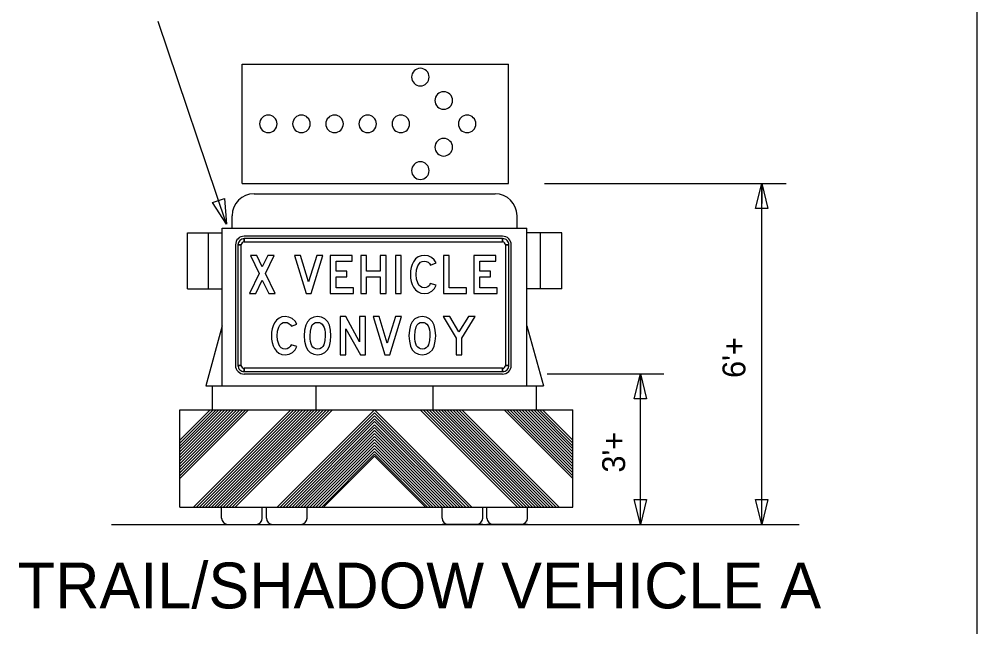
# Model space of a CAD drawing. Extents: x -747 to 834, y -5485 to -3577.
# Drawn here: x 65.7 to 316.6, y -4697.2 to -4538 of the extents above; entities that cross this region are included whole.
import ezdxf

# ---------------------------------------------------------------- set-up
doc = ezdxf.new("R2010")
doc.units = 0
doc.layers.add('Working Level 1', color=7, linetype='Continuous')

msp = doc.modelspace()

# ---------------------------------------------------------------- linework, layer by layer
at = {"layer": 'Working Level 1'}
for p, q in [((316.57, -4442.19), (316.57, -5484.51)), ((120, -4591.66), (102.14, -4538.59)), ((124.09, -4549.76), (193.86, -4549.76)), ((124.09, -4581.05), (124.09, -4549.76)), ((193.86, -4581.05), (193.86, -4549.76)), ((124.09, -4581.05), (193.86, -4581.05)), ((203.33, -4581.05), (266.6, -4581.05)), ((260.24, -4670.36), (260.24, -4581.05)), ((260.24, -4581.05), (260.24, -4586.29)), ((127.24, -4583.73), (190.38, -4583.73)), ((121.49, -4592.76), (121.49, -4589.46)), ((196.12, -4592.76), (196.12, -4589.46)), ((118.89, -4634.02), (118.89, -4592.76)), ((118.89, -4592.76), (198.72, -4592.76)), ((198.72, -4634.02), (198.72, -4592.76)), ((109.78, -4608.59), (109.78, -4593.92)), ((109.78, -4593.92), (118.89, -4593.92)), ((115.3, -4608.59), (115.3, -4593.92)), ((192.35, -4594.83), (124.64, -4594.83)), ((124.64, -4596.33), (124.64, -4595.46)), ((192.35, -4595.46), (192.35, -4596.33)), ((207.83, -4593.92), (198.72, -4593.92)), ((202.31, -4608.59), (202.31, -4593.92)), ((207.83, -4608.59), (207.83, -4593.92)), ((122.38, -4597.09), (122.38, -4628.69)), ((123.01, -4597.09), (123.88, -4597.09)), ((193.1, -4597.09), (193.98, -4597.09)), ((194.61, -4628.69), (194.61, -4597.09)), ((109.78, -4608.59), (118.89, -4608.59)), ((207.83, -4608.59), (198.72, -4608.59)), ((118.89, -4618.31), (114.58, -4634.02)), ((198.72, -4618.31), (203.04, -4634.02)), ((123.88, -4628.69), (123.01, -4628.69)), ((124.64, -4630.32), (124.64, -4629.44)), ((192.35, -4629.44), (192.35, -4630.32)), ((193.98, -4628.69), (193.1, -4628.69)), ((124.64, -4630.94), (192.35, -4630.94)), ((203.98, -4630.94), (234.6, -4630.94)), ((228.43, -4670.36), (228.43, -4630.94)), ((228.43, -4630.94), (228.43, -4636.27)), ((114.58, -4634.02), (203.04, -4634.02)), ((116.37, -4640.33), (116.37, -4634.02)), ((143.49, -4640.33), (143.49, -4634.14)), ((174.12, -4640.33), (174.12, -4634.14)), ((201.24, -4640.33), (201.24, -4634.02)), ((107.8, -4640.33), (210.75, -4640.33)), ((107.8, -4640.33), (210.75, -4640.33)), ((107.8, -4640.33), (210.75, -4640.33)), ((107.8, -4640.33), (210.75, -4640.33)), ((107.8, -4665.83), (107.8, -4640.33)), ((107.8, -4648.31), (115.78, -4640.33)), ((107.8, -4657.59), (125.06, -4640.33)), ((107.8, -4656.81), (124.28, -4640.33)), ((107.8, -4656.02), (123.5, -4640.33)), ((107.8, -4655.25), (122.73, -4640.33)), ((107.8, -4654.47), (121.95, -4640.33)), ((107.8, -4653.69), (121.16, -4640.33)), ((107.8, -4652.92), (120.39, -4640.33)), ((107.8, -4652.14), (119.61, -4640.33)), ((107.8, -4651.36), (118.83, -4640.33)), ((107.8, -4650.58), (118.05, -4640.33)), ((107.8, -4649.81), (117.28, -4640.33)), ((107.8, -4649.03), (116.5, -4640.33)), ((107.8, -4658.36), (125.81, -4640.35)), ((111.39, -4665.83), (136.89, -4640.33)), ((112.17, -4665.83), (137.66, -4640.33)), ((112.95, -4665.83), (138.45, -4640.33)), ((113.73, -4665.83), (139.23, -4640.33)), ((114.5, -4665.83), (140, -4640.33)), ((115.28, -4665.83), (140.78, -4640.33)), ((116.06, -4665.83), (141.56, -4640.33)), ((116.84, -4665.83), (142.34, -4640.33)), ((117.61, -4665.83), (143.11, -4640.33)), ((118.39, -4665.83), (143.89, -4640.33)), ((119.17, -4665.83), (144.67, -4640.33)), ((119.94, -4665.83), (145.44, -4640.33)), ((120.72, -4665.83), (146.22, -4640.33)), ((121.51, -4665.83), (146.99, -4640.34)), ((122.28, -4665.83), (147.78, -4640.33)), ((133.31, -4665.83), (158.81, -4640.33)), ((184.3, -4665.83), (158.81, -4640.33)), ((196.27, -4665.83), (170.77, -4640.33)), ((197.04, -4665.83), (171.56, -4640.34)), ((197.82, -4665.83), (172.33, -4640.33)), ((198.6, -4665.83), (173.11, -4640.33)), ((199.37, -4665.83), (173.88, -4640.33)), ((200.16, -4665.83), (174.66, -4640.33)), ((200.94, -4665.83), (175.44, -4640.33)), ((201.71, -4665.83), (176.21, -4640.33)), ((202.49, -4665.83), (176.99, -4640.33)), ((203.27, -4665.83), (177.77, -4640.33)), ((204.05, -4665.83), (178.55, -4640.33)), ((204.82, -4665.83), (179.32, -4640.33)), ((205.6, -4665.83), (180.1, -4640.33)), ((206.38, -4665.83), (180.88, -4640.33)), ((207.16, -4665.83), (181.66, -4640.33)), ((210.75, -4658.36), (192.74, -4640.35)), ((210.75, -4657.59), (193.49, -4640.33)), ((210.75, -4656.81), (194.27, -4640.33)), ((210.75, -4656.02), (195.05, -4640.33)), ((210.75, -4655.25), (195.82, -4640.33)), ((210.75, -4654.47), (196.6, -4640.33)), ((210.75, -4653.69), (197.38, -4640.33)), ((210.75, -4652.92), (198.15, -4640.33)), ((210.75, -4652.14), (198.93, -4640.33)), ((210.75, -4651.36), (199.72, -4640.33)), ((210.75, -4650.58), (200.5, -4640.33)), ((210.75, -4649.81), (201.27, -4640.33)), ((210.75, -4649.03), (202.05, -4640.33)), ((210.75, -4648.31), (202.77, -4640.33)), ((210.75, -4665.83), (210.75, -4640.33)), ((134.08, -4665.83), (158.81, -4641.1)), ((134.86, -4665.83), (158.81, -4641.88)), ((135.65, -4665.83), (158.81, -4642.66)), ((183.49, -4665.78), (158.81, -4641.1)), ((182.75, -4665.83), (158.81, -4641.88)), ((181.97, -4665.83), (158.81, -4642.66)), ((136.42, -4665.83), (158.81, -4643.43)), ((137.2, -4665.83), (158.81, -4644.22)), ((137.98, -4665.83), (158.81, -4645)), ((138.75, -4665.83), (158.81, -4645.77)), ((181.2, -4665.83), (158.81, -4643.43)), ((180.42, -4665.83), (158.81, -4644.22)), ((179.64, -4665.83), (158.81, -4645)), ((178.87, -4665.83), (158.81, -4645.77)), ((139.53, -4665.83), (158.81, -4646.55)), ((140.31, -4665.83), (158.81, -4647.33)), ((141.09, -4665.83), (158.81, -4648.11)), ((178.09, -4665.83), (158.81, -4646.55)), ((177.31, -4665.83), (158.81, -4647.33)), ((176.53, -4665.83), (158.81, -4648.11)), ((141.86, -4665.83), (158.81, -4648.88)), ((142.64, -4665.83), (158.81, -4649.66)), ((143.42, -4665.83), (158.81, -4650.44)), ((175.76, -4665.83), (158.81, -4648.88)), ((174.98, -4665.83), (158.81, -4649.66)), ((174.2, -4665.83), (158.81, -4650.44)), ((144.19, -4665.83), (158.81, -4651.21)), ((144.97, -4665.83), (158.81, -4651.99)), ((145.62, -4665.68), (158.81, -4652.49)), ((173.43, -4665.83), (158.81, -4651.21)), ((172.64, -4665.83), (158.81, -4651.99)), ((172.14, -4665.83), (158.81, -4652.49)), ((107.8, -4665.83), (210.75, -4665.83)), ((107.8, -4665.83), (210.75, -4665.83)), ((107.8, -4665.83), (210.75, -4665.83)), ((107.8, -4665.83), (210.75, -4665.83)), ((118.74, -4668.71), (118.74, -4665.83)), ((129.38, -4668.71), (129.38, -4665.83)), ((130.48, -4668.71), (130.48, -4665.83)), ((141.11, -4668.71), (141.11, -4665.83)), ((176.5, -4668.71), (176.5, -4665.83)), ((187.14, -4668.71), (187.14, -4665.83)), ((188.24, -4668.71), (188.24, -4665.83)), ((198.87, -4668.71), (198.87, -4665.83)), ((89.92, -4670.36), (270.03, -4670.36)), ((118.74, -4670.36), (129.38, -4670.36)), ((118.74, -4670.36), (129.38, -4670.36)), ((118.74, -4670.36), (129.38, -4670.36)), ((118.74, -4670.36), (129.38, -4670.36)), ((130.48, -4670.36), (141.11, -4670.36)), ((130.48, -4670.36), (141.11, -4670.36)), ((130.48, -4670.36), (141.11, -4670.36)), ((130.48, -4670.36), (141.11, -4670.36)), ((187.14, -4670.36), (176.5, -4670.36)), ((187.14, -4670.36), (176.5, -4670.36)), ((187.14, -4670.36), (176.5, -4670.36)), ((187.14, -4670.36), (176.5, -4670.36)), ((198.87, -4670.36), (188.24, -4670.36)), ((198.87, -4670.36), (188.24, -4670.36)), ((198.87, -4670.36), (188.24, -4670.36)), ((198.87, -4670.36), (188.24, -4670.36))]:
    msp.add_line(p, q, dxfattribs=at)
for points in [[(258.61, -4587.55), (260.24, -4581.05), (261.86, -4587.55)], [(119.46, -4584.98), (120, -4591.66), (116.38, -4586.02)], [(192.35, -4595.46), (124.64, -4595.46), (124.64, -4596.33), (192.35, -4596.33), (192.35, -4595.46)], [(123.01, -4597.09), (123.01, -4628.69), (123.88, -4628.69), (123.88, -4597.09), (123.01, -4597.09)], [(193.98, -4628.69), (193.98, -4597.09), (193.1, -4597.09), (193.1, -4628.69), (193.98, -4628.69)], [(132.74, -4609.88), (130.24, -4604.62), (132.53, -4599.85), (130.86, -4599.85), (129.4, -4602.87), (127.96, -4599.85), (126.28, -4599.85), (128.56, -4604.63), (126.05, -4609.88), (127.72, -4609.88), (129.4, -4606.39), (131.07, -4609.88)], [(145.27, -4599.85), (143.69, -4599.85), (141.53, -4606.78), (139.38, -4599.85), (137.8, -4599.85), (140.91, -4609.88), (142.16, -4609.88)], [(153.27, -4608.36), (148.72, -4608.36), (148.72, -4605.52), (151.56, -4605.52), (151.56, -4604.01), (148.72, -4604.01), (148.72, -4601.36), (152.97, -4601.36), (152.97, -4599.85), (147.21, -4599.85), (147.21, -4609.88), (153.27, -4609.88)], [(161.83, -4609.88), (161.83, -4599.85), (160.31, -4599.85), (160.31, -4604.01), (156.71, -4604.01), (156.71, -4599.85), (155.2, -4599.85), (155.2, -4609.88), (156.71, -4609.88), (156.71, -4605.52), (160.31, -4605.52), (160.31, -4609.88)], [(165.81, -4609.88), (165.81, -4599.85), (164.29, -4599.85), (164.29, -4609.88)], [(174.91, -4607.65), (173.39, -4607.27), (173.17, -4607.71), (172.8, -4608.06), (172.33, -4608.29), (171.81, -4608.36), (171.28, -4608.28), (170.83, -4608.04), (170.44, -4607.64), (170.14, -4607.09), (169.83, -4606.06), (169.73, -4604.86), (169.83, -4603.66), (170.15, -4602.63), (170.47, -4602.07), (170.86, -4601.68), (171.32, -4601.44), (171.86, -4601.36), (172.36, -4601.43), (172.81, -4601.64), (173.19, -4601.97), (173.45, -4602.39), (174.91, -4601.82), (174.42, -4601.01), (173.7, -4600.38), (172.83, -4599.98), (171.88, -4599.85), (170.99, -4599.95), (170.23, -4600.27), (169.57, -4600.79), (169.02, -4601.52), (168.66, -4602.24), (168.41, -4603.04), (168.26, -4603.91), (168.21, -4604.86), (168.26, -4605.8), (168.41, -4606.67), (168.66, -4607.46), (169.01, -4608.19), (169.55, -4608.93), (170.2, -4609.45), (170.96, -4609.77), (171.83, -4609.88), (172.85, -4609.72), (173.77, -4609.26), (174.48, -4608.55)], [(182.9, -4609.88), (182.9, -4608.36), (178.35, -4608.36), (178.35, -4599.85), (176.83, -4599.85), (176.83, -4609.88)], [(190.89, -4608.36), (186.34, -4608.36), (186.34, -4605.52), (189.18, -4605.52), (189.18, -4604.01), (186.34, -4604.01), (186.34, -4601.36), (190.59, -4601.36), (190.59, -4599.85), (184.83, -4599.85), (184.83, -4609.88), (190.89, -4609.88)], [(138.46, -4623.7), (136.95, -4623.32), (136.72, -4623.76), (136.35, -4624.11), (135.88, -4624.34), (135.36, -4624.41), (134.83, -4624.33), (134.38, -4624.09), (134, -4623.7), (133.69, -4623.14), (133.38, -4622.11), (133.28, -4620.91), (133.39, -4619.71), (133.7, -4618.68), (134.02, -4618.13), (134.41, -4617.73), (134.87, -4617.49), (135.41, -4617.41), (135.91, -4617.48), (136.37, -4617.69), (136.75, -4618.02), (137.01, -4618.44), (138.46, -4617.87), (137.97, -4617.06), (137.26, -4616.43), (136.39, -4616.03), (135.43, -4615.9), (134.55, -4616), (133.78, -4616.32), (133.12, -4616.84), (132.58, -4617.57), (132.22, -4618.29), (131.97, -4619.09), (131.82, -4619.96), (131.77, -4620.91), (131.81, -4621.85), (131.97, -4622.72), (132.21, -4623.52), (132.57, -4624.24), (133.1, -4624.98), (133.75, -4625.5), (134.51, -4625.82), (135.38, -4625.93), (136.4, -4625.77), (137.32, -4625.31), (138.04, -4624.6)], [(147.39, -4620.91), (147.29, -4619.48), (146.98, -4618.14), (146.53, -4617.23), (145.81, -4616.51), (144.9, -4616.05), (143.88, -4615.9), (142.86, -4616.05), (141.96, -4616.51), (141.25, -4617.23), (140.8, -4618.14), (140.49, -4619.48), (140.39, -4620.91), (140.49, -4622.33), (140.8, -4623.67), (141.25, -4624.58), (141.96, -4625.3), (142.86, -4625.77), (143.88, -4625.93), (144.9, -4625.77), (145.81, -4625.31), (146.52, -4624.6), (146.98, -4623.69), (147.28, -4622.34)], [(145.88, -4620.91), (145.79, -4622.13), (145.52, -4623.26), (145.28, -4623.74), (144.9, -4624.1), (144.43, -4624.34), (143.9, -4624.41), (143.43, -4624.36), (143.02, -4624.19), (142.68, -4623.92), (142.4, -4623.54), (142.18, -4623.05), (142.03, -4622.44), (141.93, -4621.73), (141.9, -4620.91), (141.99, -4619.7), (142.26, -4618.57), (142.5, -4618.1), (142.87, -4617.73), (143.35, -4617.49), (143.9, -4617.41), (144.36, -4617.47), (144.76, -4617.63), (145.1, -4617.9), (145.38, -4618.29), (145.6, -4618.78), (145.75, -4619.38), (145.84, -4620.09)], [(156.42, -4625.93), (156.42, -4615.9), (154.9, -4615.9), (154.9, -4622.49), (151.25, -4615.9), (149.79, -4615.9), (149.79, -4625.93), (151.31, -4625.93), (151.31, -4619.12), (155.08, -4625.93)], [(165.89, -4615.9), (164.3, -4615.9), (162.15, -4622.83), (160, -4615.9), (158.42, -4615.9), (161.52, -4625.93), (162.77, -4625.93)], [(174.82, -4620.91), (174.72, -4619.48), (174.41, -4618.14), (173.96, -4617.23), (173.24, -4616.51), (172.34, -4616.05), (171.32, -4615.9), (170.3, -4616.05), (169.39, -4616.51), (168.68, -4617.23), (168.23, -4618.14), (167.92, -4619.48), (167.82, -4620.91), (167.92, -4622.33), (168.23, -4623.67), (168.68, -4624.58), (169.39, -4625.3), (170.3, -4625.77), (171.32, -4625.93), (172.33, -4625.77), (173.24, -4625.31), (173.95, -4624.6), (174.41, -4623.69), (174.72, -4622.34)], [(173.31, -4620.91), (173.22, -4622.13), (172.95, -4623.26), (172.71, -4623.74), (172.34, -4624.1), (171.86, -4624.34), (171.33, -4624.41), (170.86, -4624.36), (170.45, -4624.19), (170.11, -4623.92), (169.83, -4623.54), (169.61, -4623.05), (169.46, -4622.44), (169.36, -4621.73), (169.33, -4620.91), (169.42, -4619.7), (169.69, -4618.57), (169.93, -4618.1), (170.3, -4617.73), (170.78, -4617.49), (171.33, -4617.41), (171.79, -4617.47), (172.19, -4617.63), (172.53, -4617.9), (172.81, -4618.29), (173.03, -4618.78), (173.18, -4619.38), (173.28, -4620.09)], [(185.16, -4615.9), (183.38, -4615.9), (180.92, -4619.9), (178.52, -4615.9), (176.75, -4615.9), (180.16, -4621.53), (180.16, -4625.93), (181.68, -4625.93), (181.68, -4621.57)], [(124.64, -4630.32), (192.35, -4630.32), (192.35, -4629.44), (124.64, -4629.44), (124.64, -4630.32)], [(226.8, -4637.44), (228.43, -4630.94), (230.05, -4637.44)], [(230.05, -4663.86), (228.43, -4670.36), (226.8, -4663.86)], [(261.86, -4663.86), (260.24, -4670.36), (258.61, -4663.86)]]:
    msp.add_lwpolyline(points, close=True, dxfattribs=at)
for centre, radius, start, end in [((170.81, -4553.14), 2.3, 0, 180), ((170.81, -4553.14), 2.3, 180, 0), ((176.93, -4559.27), 2.3, 0, 180), ((176.93, -4559.27), 2.3, 180, 0), ((130.97, -4565.4), 2.3, 0, 180), ((130.97, -4565.4), 2.3, 180, 0), ((139.65, -4565.4), 2.3, 0, 180), ((139.65, -4565.4), 2.3, 180, 0), ((148.33, -4565.4), 2.3, 0, 180), ((148.33, -4565.4), 2.3, 180, 0), ((157.01, -4565.4), 2.3, 0, 180), ((157.01, -4565.4), 2.3, 180, 0), ((165.69, -4565.4), 2.3, 0, 180), ((165.69, -4565.4), 2.3, 180, 0), ((183.05, -4565.4), 2.3, 0, 180), ((183.05, -4565.4), 2.3, 180, 0), ((176.93, -4571.52), 2.3, 0, 180), ((176.93, -4571.52), 2.3, 180, 0), ((170.81, -4577.64), 2.3, 0, 180), ((170.81, -4577.64), 2.3, 180, 0), ((127.23, -4589.46), 5.74, 90, 180), ((190.38, -4589.46), 5.74, 0, 90), ((124.64, -4597.09), 2.26, 90.0002, 179.9998), ((124.64, -4597.09), 1.63, 90.0002, 179.9998), ((192.35, -4597.09), 2.26, 0, 90.0002), ((192.35, -4597.09), 1.63, 0, 90.0002), ((124.64, -4597.09), 0.752, 90.0002, 179.9998), ((192.35, -4597.09), 0.752, 0, 90.0002), ((124.64, -4628.69), 2.26, 179.9998, 270.0001), ((124.64, -4628.69), 1.63, 179.9998, 270.0001), ((124.64, -4628.69), 0.752, 179.9998, 270.0001), ((192.35, -4628.69), 2.26, 270.0001, 0.0003), ((192.35, -4628.69), 1.63, 270.0001, 0.0003), ((192.35, -4628.69), 0.752, 270.0001, 0.0003), ((120.39, -4668.71), 1.65, 180, 270), ((127.73, -4668.71), 1.65, 270, 0), ((132.13, -4668.71), 1.65, 180, 270), ((139.46, -4668.71), 1.65, 270, 0), ((178.15, -4668.71), 1.65, 180, 270), ((185.49, -4668.71), 1.65, 270, 0), ((189.89, -4668.71), 1.65, 180, 270), ((197.22, -4668.71), 1.65, 270, 0)]:
    msp.add_arc(centre, radius, start, end, dxfattribs=at)

# ---------------------------------------------------------------- texts
for s, p in [("6'+", (255.94, -4631.97)), ("3'+", (224.44, -4656.77))]:
    msp.add_text(s, height=6, rotation=90, dxfattribs=at).set_placement(p)
msp.add_text('TRAIL/SHADOW VEHICLE A', height=12, dxfattribs=at).set_placement((65.35, -4692.36))

doc.saveas('drawing.dxf')
